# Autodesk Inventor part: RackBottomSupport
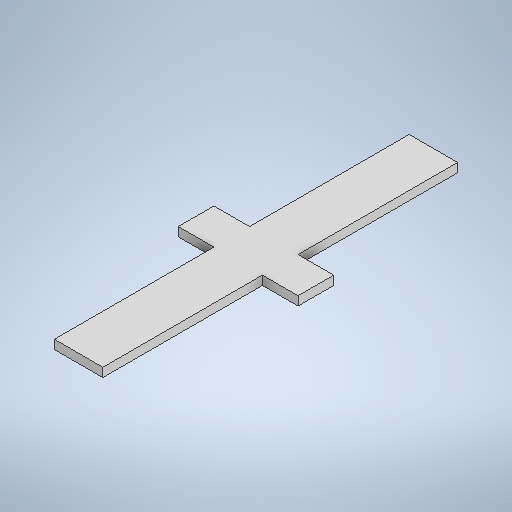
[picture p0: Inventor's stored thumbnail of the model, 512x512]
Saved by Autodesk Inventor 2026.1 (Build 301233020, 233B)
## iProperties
Created: 2026-11
Part Number: RackBottomSupport
Material: Generic
Document SubType Name: Modeling
Designer: hp
Density: 1 g/cm^3
Appearance: Default
Author: hp
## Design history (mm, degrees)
sketch "Sketch1"
  geometry: L1 (-13.134, 99.677)-(14.066, 99.677); L2 (14.066, 99.677)-(14.066, -99.323); L3 (14.066, -99.323)-(-13.134, -99.323); L4 (-13.134, -99.323)-(-13.134, 99.677); L5 (-3.134, 88.677)-(4.066, 88.677); L6 (-3.134, -88.323)-(-3.134, 88.677); L7 (4.066, 88.677)-(4.066, -88.323); L8 (4.066, -88.323)-(-3.134, -88.323); L9 (14.066, 10.177)-(34.066, 10.177); L10 (34.066, 10.177)-(34.066, -9.823); L11 (34.066, -9.823)-(14.066, -9.823); L12 (14.066, -9.823)-(14.066, 10.177); L13 (-13.134, 10.177)-(-33.134, 10.177); L14 (-33.134, 10.177)-(-33.134, -9.823); L15 (-33.134, -9.823)-(-13.134, -9.823); L16 (-13.134, -9.823)-(-13.134, 10.177); 8 further points
  constraints: 32 end point, 6 parallel, 5 midpoint, 3 horizontal, 3 perpendicular, 3 point on line, 2 horizontal alignment, 1 collinear, 1 vertical alignment
  dimensions: "d0" = 10 distance between parallel lines of L7 L2; "d1" = 11 distance between parallel lines of L8 L3; "d2" = 20 distance of L10.end L11.end; "d3" = 20 distance of L9.end L10.end; "d4" = 20 distance of L14.end L15.end (= d2)
extrude "Extrusion1" new body sketch "Sketch1" distance "d5" = 5; taper "d6" = 0 deg
body "Solid1"
